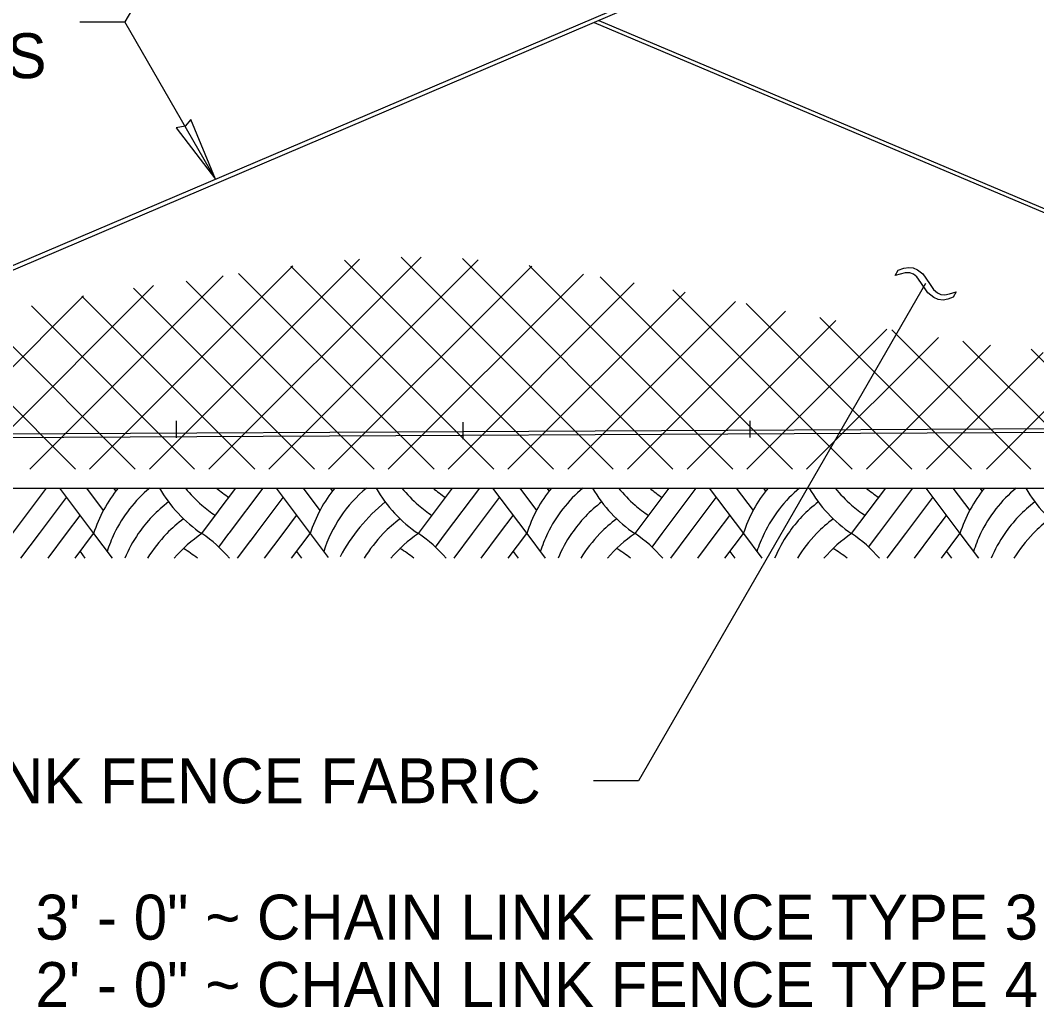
# Model space of a CAD drawing. Extents: x 99862 to 104211, y 98939 to 105076.
# Drawn here: x 100439.3 to 100801.3, y 101093.9 to 101445.4 of the extents above; entities that cross this region are included whole.
import ezdxf

# ---------------------------------------------------------------- set-up
doc = ezdxf.new("R2010")
doc.units = 0
for name, color, linetype in [('Level 10', 7, 'Continuous'), ('Level 15', 7, 'Continuous'), ('Level 2', 7, 'Continuous'), ('Level 20', 7, 'Continuous'), ('Level 4', 7, 'Continuous')]:
    doc.layers.add(name, color=color, linetype=linetype)

msp = doc.modelspace()

# ---------------------------------------------------------------- linework, layer by layer
at = {"layer": 'Level 10'}
for p, q in [((100309.46, 101278.85), (100970.86, 101278.85)), ((100436.47, 101262.65), (100448.63, 101278.85)), ((100453.24, 101278.85), (100465.4, 101262.65)), ((100462.88, 101278.85), (100468.87, 101270.87)), ((100472.53, 101278.85), (100473.34, 101277.76)), ((100509.83, 101270.47), (100516.12, 101278.85)), ((100513.82, 101262.93), (100525.76, 101278.85)), ((100530.38, 101278.85), (100548.95, 101254.09)), ((100540.02, 101278.85), (100546.01, 101270.87)), ((100549.66, 101278.85), (100550.48, 101277.76)), ((100581.1, 101262.65), (100593.25, 101278.85)), ((100590.74, 101262.65), (100602.9, 101278.85)), ((100607.51, 101278.85), (100619.67, 101262.65)), ((100617.15, 101278.85), (100623.14, 101270.87)), ((100626.79, 101278.85), (100627.61, 101277.76)), ((100658.23, 101262.65), (100670.39, 101278.85)), ((100667.87, 101262.65), (100680.03, 101278.85)), ((100684.64, 101278.85), (100696.8, 101262.65)), ((100694.29, 101278.85), (100700.27, 101270.87)), ((100703.93, 101278.85), (100704.74, 101277.76)), ((100735.37, 101262.65), (100747.52, 101278.85)), ((100745.01, 101262.65), (100757.16, 101278.85)), ((100761.78, 101278.85), (100773.93, 101262.65)), ((100771.42, 101278.85), (100777.41, 101270.87)), ((100781.06, 101278.85), (100781.88, 101277.76)), ((100446.12, 101262.65), (100455.76, 101275.5)), ((100523.25, 101262.65), (100532.89, 101275.5)), ((100600.38, 101262.65), (100610.02, 101275.5)), ((100677.52, 101262.65), (100687.16, 101275.5)), ((100754.65, 101262.65), (100764.29, 101275.5)), ((100503.97, 101262.65), (100509.92, 101270.59)), ((100455.76, 101262.65), (100460.58, 101269.07)), ((100532.89, 101262.65), (100537.71, 101269.07)), ((100610.02, 101262.65), (100614.85, 101269.07)), ((100687.16, 101262.65), (100691.98, 101269.07)), ((100764.29, 101262.65), (100769.11, 101269.07)), ((100513.61, 101262.65), (100513.88, 101263.01)), ((100439.53, 101253.86), (100446.12, 101262.65)), ((100449.17, 101253.86), (100455.76, 101262.65)), ((100458.81, 101253.86), (100465.4, 101262.65)), ((100465.4, 101262.65), (100471.99, 101253.86)), ((100510.01, 101257.85), (100513.61, 101262.65)), ((100516.66, 101253.86), (100521.4, 101260.19)), ((100521.27, 101260.01), (100523.25, 101262.65)), ((100526.3, 101253.86), (100532.89, 101262.65)), ((100535.94, 101253.86), (100542.53, 101262.65)), ((100587.14, 101257.85), (100590.74, 101262.65)), ((100593.79, 101253.86), (100600.38, 101262.65)), ((100603.44, 101253.86), (100610.02, 101262.65)), ((100613.08, 101253.86), (100619.67, 101262.65)), ((100619.67, 101262.65), (100626.25, 101253.86)), ((100664.28, 101257.85), (100667.87, 101262.65)), ((100670.93, 101253.86), (100677.52, 101262.65)), ((100680.57, 101253.86), (100687.16, 101262.65)), ((100690.21, 101253.86), (100696.8, 101262.65)), ((100696.8, 101262.65), (100703.39, 101253.86)), ((100741.41, 101257.85), (100745.01, 101262.65)), ((100748.06, 101253.86), (100754.65, 101262.65)), ((100757.7, 101253.86), (100764.29, 101262.65)), ((100767.35, 101253.86), (100773.93, 101262.65)), ((100773.93, 101262.65), (100780.52, 101253.86)), ((100460.58, 101256.22), (100462.34, 101253.86)), ((100537.71, 101256.22), (100539.48, 101253.86)), ((100614.85, 101256.22), (100616.61, 101253.86)), ((100691.98, 101256.22), (100693.75, 101253.86)), ((100769.11, 101256.22), (100770.88, 101253.86))]:
    msp.add_line(p, q, dxfattribs=at)
for centre, radius, start, end in [((100511.9, 101247.86), 48.8, 140.5627, 162.3566), ((100516.72, 101241.43), 48.8, 129.9188, 154.2266), ((100531.19, 101303.15), 48.8, 209.8569, 236.0964), ((100536.01, 101309.58), 48.8, 219.0175, 228.9599), ((100540.83, 101316), 48.8, 229.5771, 236.0964), ((100589.04, 101247.86), 48.8, 140.5627, 162.3566), ((100593.86, 101241.43), 48.8, 129.9188, 162.3566), ((100608.32, 101303.15), 48.8, 209.8569, 236.0964), ((100613.14, 101309.58), 48.8, 219.0175, 228.9599), ((100617.96, 101316), 48.8, 229.5771, 236.0964), ((100666.17, 101247.86), 48.8, 140.5627, 162.3566), ((100670.99, 101241.43), 48.8, 129.9188, 154.2266), ((100685.45, 101303.15), 48.8, 209.8569, 236.0964), ((100690.27, 101309.58), 48.8, 219.0175, 228.9599), ((100695.09, 101316), 48.8, 229.5771, 236.0964), ((100743.3, 101247.86), 48.8, 140.5627, 162.3566), ((100748.12, 101241.43), 48.8, 129.9188, 154.2266), ((100762.59, 101303.15), 48.8, 209.8569, 236.0964), ((100767.41, 101309.58), 48.8, 219.0175, 228.9599), ((100772.23, 101316), 48.8, 229.5771, 236.0964), ((100820.44, 101247.86), 48.8, 140.5627, 162.3566), ((100825.26, 101241.43), 48.8, 129.9188, 154.2266), ((100839.72, 101303.15), 48.8, 209.8569, 236.0964), ((100521.54, 101235), 48.8, 127.1006, 145.4911), ((100610.29, 101223.7), 64.86, 129.2593, 151.724), ((100675.81, 101235), 48.8, 127.1006, 145.4911), ((100752.95, 101235), 48.8, 127.1006, 145.4911), ((100830.08, 101235), 48.8, 127.1006, 145.4911), ((100536.01, 101309.58), 48.8, 228.9599, 236.0964), ((100613.14, 101309.58), 48.8, 228.9599, 236.0964), ((100690.27, 101309.58), 48.8, 228.9599, 236.0964), ((100767.41, 101309.58), 48.8, 228.9599, 236.0964), ((100526.37, 101228.57), 48.8, 126.331, 135.7128), ((100603.5, 101228.57), 48.8, 126.331, 135.7128), ((100680.63, 101228.57), 48.8, 126.331, 135.7128), ((100757.77, 101228.57), 48.8, 126.331, 135.7128), ((100834.9, 101228.57), 48.8, 126.331, 135.7128), ((100516.72, 101241.43), 48.8, 154.2265, 162.3566), ((100521.54, 101235), 48.8, 145.491, 157.2609), ((100526.37, 101228.57), 48.8, 135.7127, 148.7846), ((100531.19, 101222.14), 48.8, 123.9036, 139.4601), ((100476.75, 101222.14), 48.8, 40.5399, 56.0963), ((100603.5, 101228.57), 48.8, 135.7127, 148.7846), ((100608.32, 101222.14), 48.8, 123.9036, 139.4601), ((100553.88, 101222.14), 48.8, 40.5399, 56.0963), ((100670.99, 101241.43), 48.8, 154.2265, 162.3566), ((100675.81, 101235), 48.8, 145.491, 157.2609), ((100680.63, 101228.57), 48.8, 135.7127, 148.7846), ((100685.45, 101222.14), 48.8, 123.9036, 139.4601), ((100631.01, 101222.14), 48.8, 40.5399, 56.0963), ((100748.12, 101241.43), 48.8, 154.2265, 162.3566), ((100752.95, 101235), 48.8, 145.491, 157.2609), ((100757.77, 101228.57), 48.8, 135.7127, 148.7846), ((100762.59, 101222.14), 48.8, 123.9036, 139.4601), ((100708.15, 101222.14), 48.8, 40.5399, 56.0963), ((100825.26, 101241.43), 48.8, 154.2265, 162.3566), ((100830.08, 101235), 48.8, 145.491, 157.2609), ((100834.9, 101228.57), 48.8, 135.7127, 148.7846), ((100471.93, 101215.72), 48.8, 51.4164, 58.5465), ((100549.06, 101215.72), 48.8, 51.4164, 58.5465), ((100626.19, 101215.72), 48.8, 51.4164, 58.5465), ((100703.33, 101215.72), 48.8, 51.4164, 58.5465)]:
    msp.add_arc(centre, radius, start, end, dxfattribs=at)
at = {"layer": 'Level 15'}
for p, q in [((100509.26, 101501.46), (100476.54, 101444.79)), ((100460.54, 101444.79), (100476.54, 101444.79)), ((100508.85, 101388.82), (100476.54, 101444.79)), ((100751.93, 101356.42), (100753.95, 101357.16)), ((100753.95, 101357.16), (100755.71, 101357.43)), ((100755.71, 101357.43), (100757.31, 101357.25)), ((100757.31, 101357.25), (100758.84, 101356.61)), ((100750.88, 101354.59), (100751.93, 101356.42)), ((100754.45, 101355.52), (100750.88, 101354.59)), ((100756.1, 101355.46), (100754.45, 101355.52)), ((100757.44, 101354.98), (100756.1, 101355.46)), ((100758.6, 101354.03), (100757.44, 101354.98)), ((100759.98, 101352.04), (100758.6, 101354.03)), ((100758.84, 101356.61), (100760.77, 101355.07)), ((100760.77, 101355.07), (100763.04, 101351.66)), ((100761.68, 101351.64), (100659.48, 101174.63)), ((100762.51, 101348.42), (100759.98, 101352.04)), ((100763.04, 101351.66), (100764.5, 101349.57)), ((100764.5, 101349.57), (100765.96, 101348.32)), ((100764.59, 101346.67), (100762.51, 101348.42)), ((100766.22, 101345.99), (100764.59, 101346.67)), ((100765.96, 101348.32), (100767.19, 101347.82)), ((100767.91, 101345.8), (100766.22, 101345.99)), ((100767.19, 101347.82), (100768.55, 101347.67)), ((100769.68, 101346.09), (100767.91, 101345.8)), ((100768.55, 101347.67), (100770.26, 101347.95)), ((100771.51, 101346.85), (100769.68, 101346.09)), ((100770.26, 101347.95), (100772.57, 101348.68)), ((100772.57, 101348.68), (100771.51, 101346.85)), ((100659.48, 101174.63), (100643.49, 101174.63))]:
    msp.add_line(p, q, dxfattribs=at)
msp.add_lwpolyline([(100508.85, 101388.82), (100500.02, 101410.08), (100497.96, 101407.68), (100494.85, 101407.1)], close=True, dxfattribs=at)
at = {"layer": 'Level 2'}
for p, q in [((100961.07, 101581.33), (100370.56, 101329.95)), ((100960.97, 101579.87), (100370.46, 101328.2)), ((100643.67, 101444.64), (100915.85, 101329.57)), ((100645.33, 101445.35), (100915.77, 101331.02)), ((100327.66, 101297.65), (100958.91, 101300.79)), ((100328.32, 101296.35), (100958.26, 101299.48))]:
    msp.add_line(p, q, dxfattribs=at)
at = {"layer": 'Level 4'}
for p, q in [((100506.5, 101285.55), (100582.05, 101361.11)), ((100650.45, 101285.55), (100574.93, 101361.07)), ((100671.72, 101285.55), (100596.75, 101360.53)), ((100463.94, 101285.55), (100536.33, 101357.94)), ((100485.26, 101285.55), (100560.12, 101360.37)), ((100527.78, 101285.55), (100602.33, 101360.09)), ((100607.91, 101285.55), (100535.62, 101357.85)), ((100549.06, 101285.55), (100621.43, 101357.91)), ((100629.15, 101285.55), (100554.78, 101359.94)), ((100693, 101285.55), (100620.52, 101358.04)), ((100442.66, 101285.55), (100511.58, 101354.47)), ((100586.66, 101285.55), (100516.96, 101355.26)), ((100570.33, 101285.55), (100639.84, 101355.06)), ((100714.26, 101285.55), (100645.78, 101354.04)), ((100421.38, 101285.55), (100486.76, 101350.93)), ((100544.11, 101285.55), (100479.63, 101350.03)), ((100565.38, 101285.55), (100498.4, 101352.54)), ((100591.63, 101285.55), (100657.97, 101351.88)), ((100400.1, 101285.55), (100461.82, 101347.27)), ((100522.83, 101285.55), (100461.22, 101347.16)), ((100612.93, 101285.55), (100676.03, 101348.64)), ((100735.56, 101285.55), (100671.68, 101349.43)), ((100501.38, 101285.55), (100443.26, 101343.74)), ((100634.24, 101285.55), (100693.98, 101345.28)), ((100756.84, 101285.55), (100697.85, 101344.55)), ((100480.27, 101285.55), (100425.56, 101340.26)), ((100655.49, 101285.55), (100711.84, 101341.89)), ((100778.11, 101285.55), (100724.06, 101339.61)), ((100459, 101285.55), (100407.44, 101337.11)), ((100676.77, 101285.55), (100729.78, 101338.56)), ((100698.06, 101285.55), (100747.93, 101335.42)), ((100799.16, 101285.55), (100749.63, 101335.14)), ((100719.35, 101285.55), (100766.31, 101332.51)), ((100740.65, 101285.55), (100784.88, 101329.76)), ((100820.67, 101285.55), (100775.02, 101331.2)), ((100841.95, 101285.55), (100799.25, 101328.25)), ((100762.06, 101285.55), (100803.59, 101327.08)), ((100783.34, 101285.55), (100822.3, 101324.51)), ((100494.92, 101296.72), (100494.92, 101302.8)), ((100699.22, 101296.81), (100699.22, 101302.78)), ((100597.07, 101296.26), (100597.07, 101302.28))]:
    msp.add_line(p, q, dxfattribs=at)

# ---------------------------------------------------------------- texts
at = {"layer": 'Level 20'}
msp.add_text('WIRES', height=16, dxfattribs=at).set_placement((100378.52, 101424.79))
for s, p in [('CHAIN LINK FENCE FABRIC', (100341.72, 101166.63)), ('3\' - 0" ~ CHAIN LINK FENCE TYPE 3 ', (100444.7, 101118.09)), ('2\' - 0" ~ CHAIN LINK FENCE TYPE 4 ', (100444.7, 101094.09))]:
    msp.add_text(s, height=16, rotation=360, dxfattribs=at).set_placement(p)

doc.saveas('drawing.dxf')
